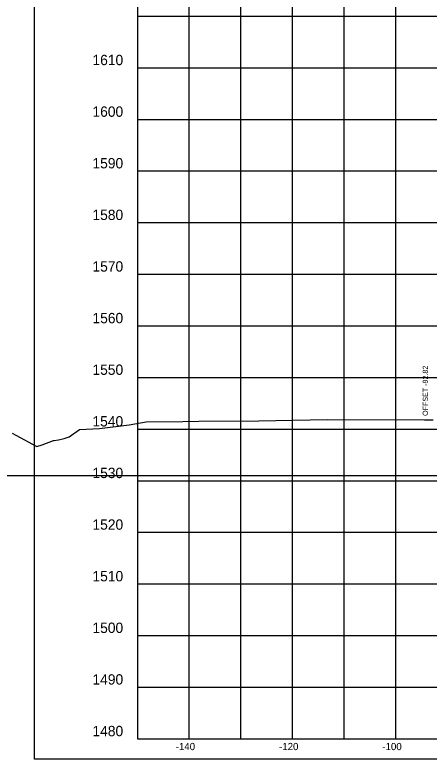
# Model space of a CAD drawing. Extents: x -26 to 2998798, y -429 to 819149.
# Drawn here: x 126.2 to 206.4, y 1945.1 to 2089.2 of the extents above; entities that cross this region are included whole.
import ezdxf

# ---------------------------------------------------------------- set-up
doc = ezdxf.new("R2010")
doc.units = 0
for name, color, linetype in [('DESIGN - SCRATCH - User 4', 7, 'Continuous'), ('DESIGN - SHEET - Corner Text', 7, 'Continuous'), ('DESIGN - SHEET - Light Grid', 7, 'Continuous'), ('DESIGN - SHEET - Linework', 7, 'Continuous'), ('DESIGN - SHEET - Plot Shape', 7, 'Continuous'), ('SURVEY - GROUND - Top of Ground', 7, 'Continuous')]:
    doc.layers.add(name, color=color, linetype=linetype)

msp = doc.modelspace()

# ---------------------------------------------------------------- linework, layer by layer
at = {"layer": 'DESIGN - SHEET - Light Grid'}
msp.add_line((0, 2000), (300, 2000), dxfattribs=at)
at = {"layer": 'DESIGN - SHEET - Linework'}
for p, q in [((160, 1949), (160, 2159)), ((170, 1949), (170, 2159)), ((180, 1949), (180, 2159)), ((190, 1949), (190, 2159)), ((200, 1949), (200, 2159)), ((150, 2089), (450, 2089)), ((150, 2079), (450, 2079)), ((150, 2069), (450, 2069)), ((150, 2059), (450, 2059)), ((150, 2049), (450, 2049)), ((150, 2039), (450, 2039)), ((150, 2029), (450, 2029)), ((150, 2019), (450, 2019)), ((150, 2009), (450, 2009)), ((150, 1999), (450, 1999)), ((150, 1989), (450, 1989)), ((150, 1979), (450, 1979)), ((150, 1969), (450, 1969)), ((150, 1959), (450, 1959))]:
    msp.add_line(p, q, dxfattribs=at)
msp.add_lwpolyline([(150, 2159), (150, 1949), (450, 1949), (450, 2159)], dxfattribs=at)
at = {"layer": 'DESIGN - SHEET - Plot Shape'}
msp.add_lwpolyline([(130, 2162.94), (470, 2162.94), (470, 1945.06), (130, 1945.06)], close=True, dxfattribs=at)
at = {"layer": 'SURVEY - GROUND - Top of Ground'}
msp.add_lwpolyline([(125.73, 2008.2), (126.42, 2007.81), (130.51, 2005.59), (131.51, 2005.97), (133.71, 2006.76), (133.86, 2006.77), (134.7, 2006.89), (135.78, 2007.2), (136.76, 2007.49), (138.72, 2008.92), (142.6, 2009.11), (148.36, 2009.8), (151.63, 2010.38), (158.73, 2010.48), (161.85, 2010.53), (173.49, 2010.57), (186.67, 2010.83), (205.5, 2010.81), (207.18, 2010.79)], dxfattribs=at)

# ---------------------------------------------------------------- texts
at = {"layer": 'DESIGN - SCRATCH - User 4'}
msp.add_text('OFFSET -92.82', height=1, rotation=90, dxfattribs=at).set_placement((206.18, 2011.54))
at = {"layer": 'DESIGN - SHEET - Corner Text'}
for s, height, p in [('1610', 2, (141.25, 2079.5)), ('1600', 2, (141.25, 2069.5)), ('1590', 2, (141.25, 2059.5)), ('1580', 2, (141.25, 2049.5)), ('1570', 2, (141.25, 2039.5)), ('1560', 2, (141.25, 2029.5)), ('1550', 2, (141.25, 2019.5)), ('1540', 2, (141.25, 2009.5)), ('1530', 2, (141.25, 1999.5)), ('1520', 2, (141.25, 1989.5)), ('1510', 2, (141.25, 1979.5)), ('1500', 2, (141.25, 1969.5)), ('1490', 2, (141.25, 1959.5)), ('1480', 2, (141.25, 1949.5)), ('-140', 1.4, (157.37, 1946.8)), ('-120', 1.4, (177.37, 1946.8)), ('-100', 1.4, (197.37, 1946.8))]:
    msp.add_text(s, height=height, dxfattribs=at).set_placement(p)

doc.saveas('drawing.dxf')
